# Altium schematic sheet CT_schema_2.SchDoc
size 403 x 258 mm
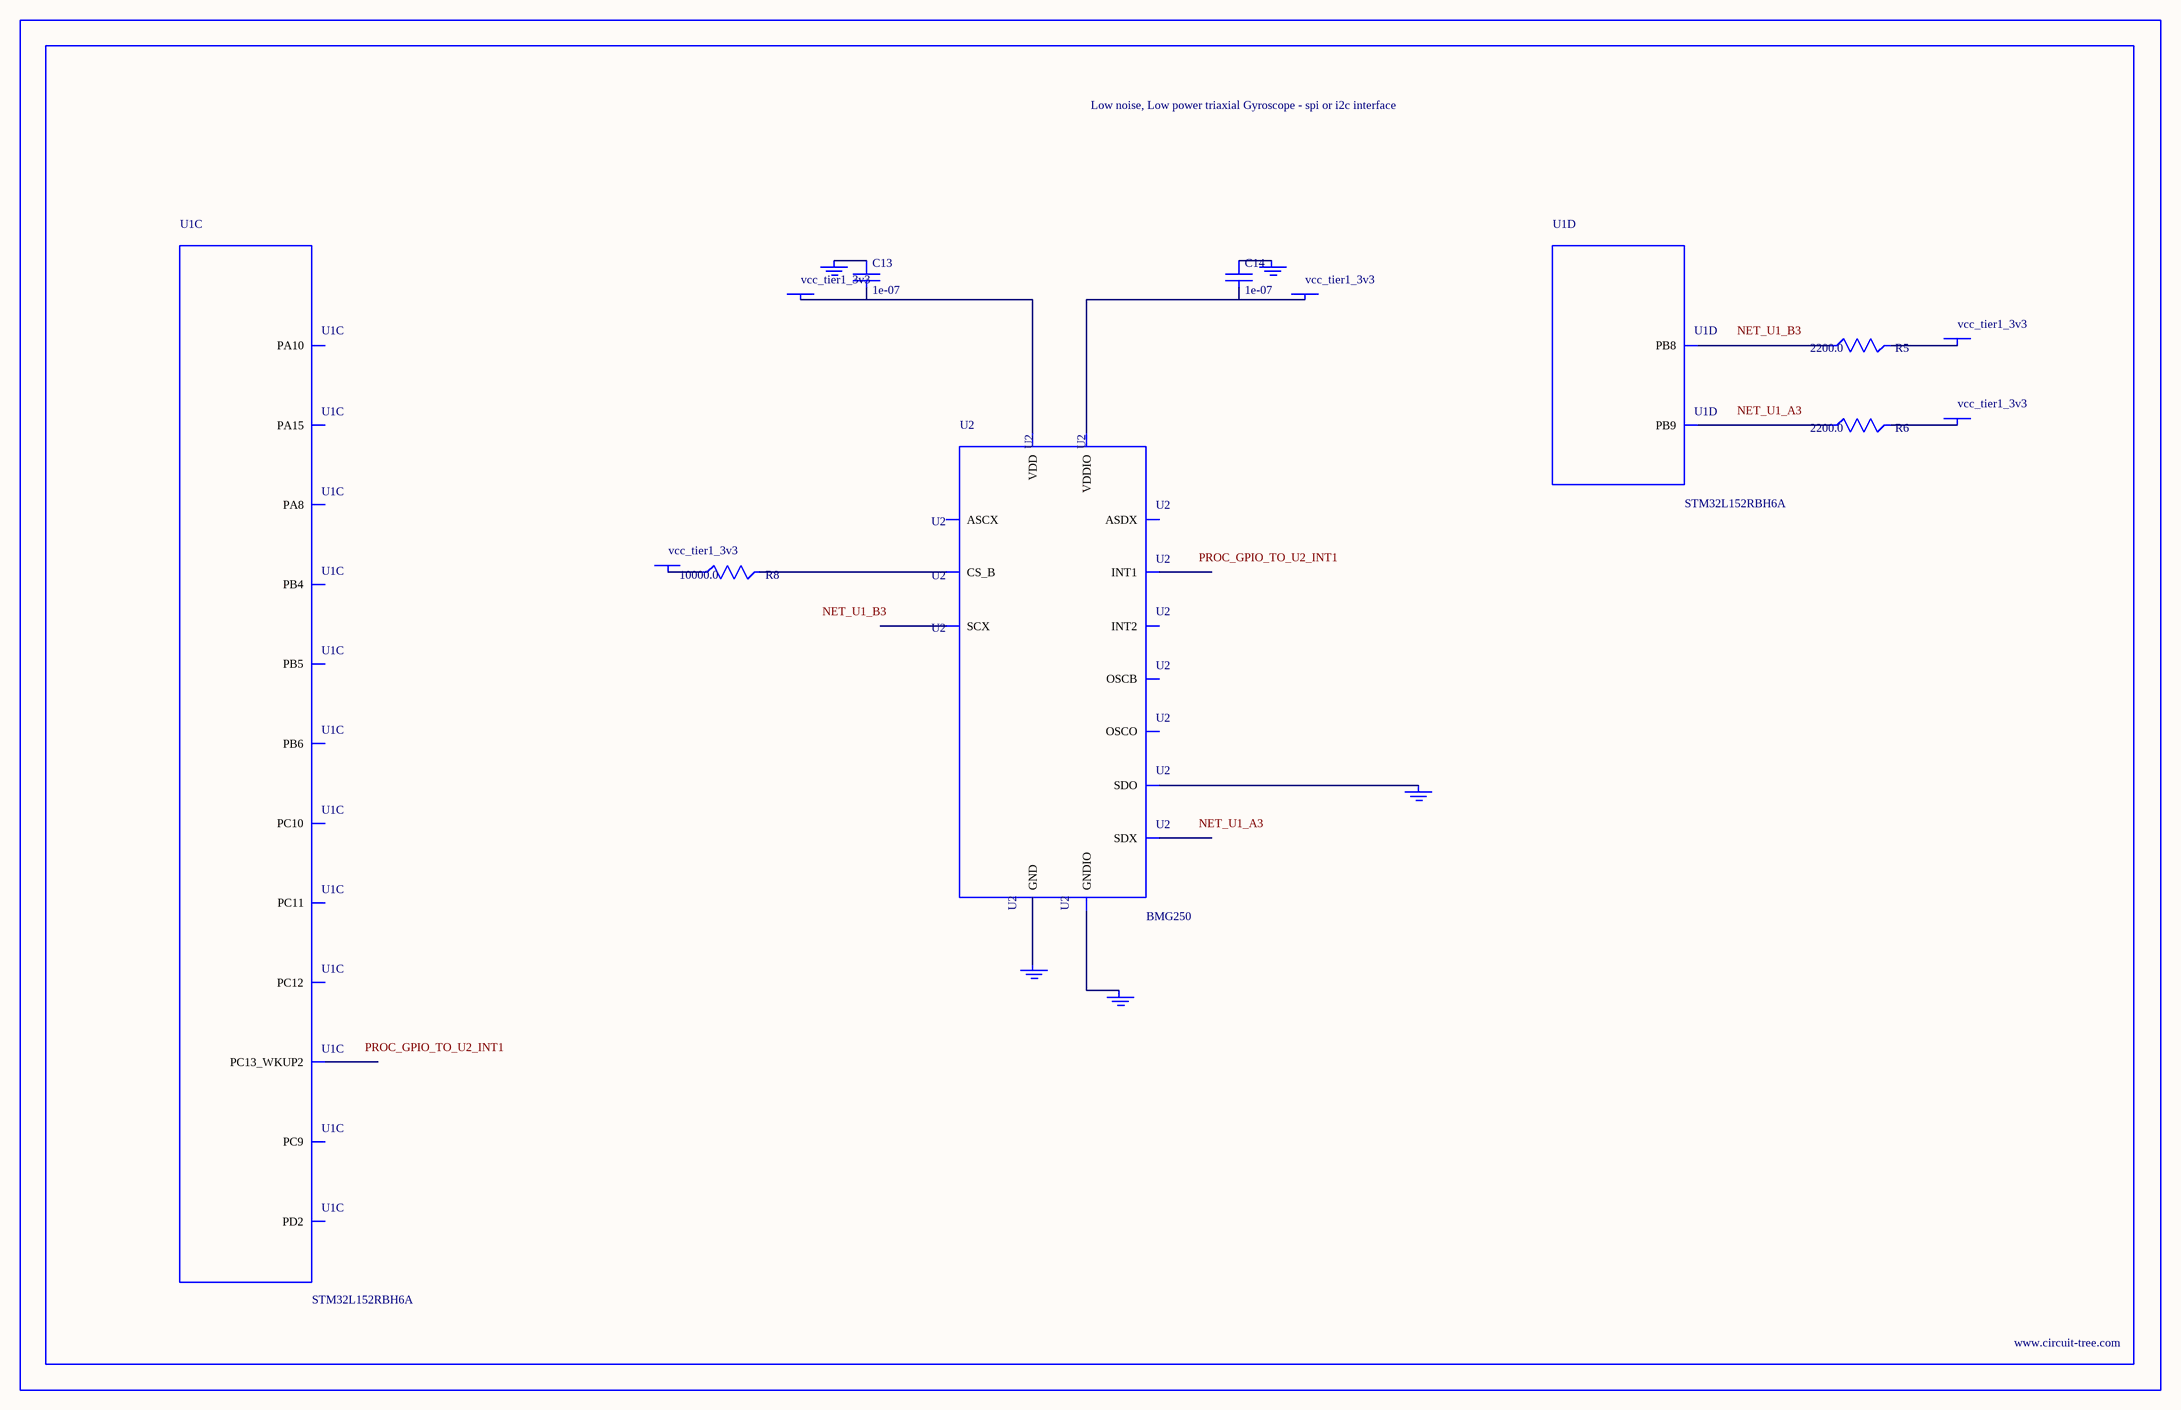
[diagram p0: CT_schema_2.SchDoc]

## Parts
BORDER1  (no value)
C13  1e-07  [C0402]
C14  1e-07  [C0402]
GND_INSTANCE_1_0  (no value)
GND_INSTANCE_1_1  (no value)
GND_INSTANCE_1_2  (no value)
GND_INSTANCE_1_3  (no value)
GND_INSTANCE_1_4  (no value)
POWER_INSTANCE_1_0  vcc_tier1_3v3
POWER_INSTANCE_1_1  vcc_tier1_3v3
POWER_INSTANCE_1_2  vcc_tier1_3v3
POWER_INSTANCE_1_3  vcc_tier1_3v3
POWER_INSTANCE_1_4  vcc_tier1_3v3
R5  2200.0  [R0603]
R6  2200.0  [R0603]
R8  10000.0  [R0603]
U1  STM32L152RBH6A  [TFBGA64]  (parts C,D of 7)
U2  BMG250  [LGA-14]

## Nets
NetC13_1: C13.1 GND_INSTANCE_1_3.0(GND)
NetC13_2: C13.2 POWER_INSTANCE_1_1.0(PWR) U2.8(VDD)
NetC14_1: C14.1 GND_INSTANCE_1_1.0(GND)
NetC14_2: C14.2 POWER_INSTANCE_1_0.0(PWR) U2.5(VDDIO)
NetGND_INSTANCE_1_0_0: GND_INSTANCE_1_0.0(GND) U2.1(SDO)
NetGND_INSTANCE_1_2_0: GND_INSTANCE_1_2.0(GND) U2.6(GNDIO)
NetGND_INSTANCE_1_4_0: GND_INSTANCE_1_4.0(GND) U2.7(GND)
NetPOWER_INSTANCE_1_2_0: POWER_INSTANCE_1_2.0(PWR) R8.1
NetPOWER_INSTANCE_1_3_0: POWER_INSTANCE_1_3.0(PWR) R5.2
NetPOWER_INSTANCE_1_4_0: POWER_INSTANCE_1_4.0(PWR) R6.2
NetR5_1: R5.1 U1.B3(PB8)
NetR6_1: R6.1 U1.A3(PB9)
NetR8_2: R8.2 U2.12(CS_B)

Not connected (* = marked no-connect by the designer): U1 A2(PC13_WKUP2) A4(PB4) A6(PA15) B5(PD2) B6(PC11) B7(PC10) C4(PB5) C5(PC12) C6(PA10) D3(PB6) D7(PA8) D8(PC9); U2 2(ASDX) 3(ASCX) 4(INT1) 9(INT2) 10(OSCB) 11(OSCO) 13(SCX) 14(SDX)

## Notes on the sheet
- Labels drawn without touching a wire or pin: NET_U1_A3, NET_U1_B3, PROC_GPIO_TO_U2_INT1

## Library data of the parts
BORDER1 = BORDER_PAGE1
C13 C14 = C0402C104K3RACTU
GND_INSTANCE_1_0-GND_INSTANCE_1_4 = GND
POWER_INSTANCE_1_0-POWER_INSTANCE_1_4 = PWR
R5 R6 = RC0603JR-072K2L
R8 = RC0603JR-0710KL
